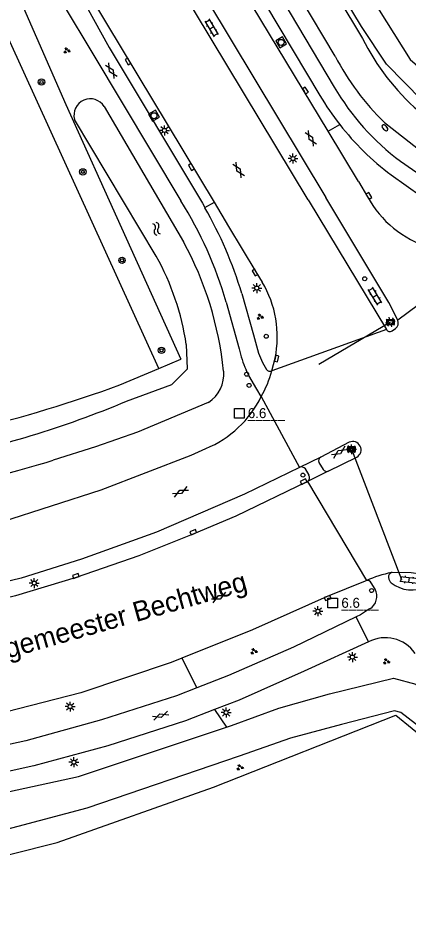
# Model space of a CAD drawing. Extents: x 133000 to 136000, y 400500 to 403500.
# Drawn here: x 133531.3 to 133580.3, y 400943.8 to 401055.6 of the extents above; entities that cross this region are included whole.
import ezdxf

# ---------------------------------------------------------------- set-up
doc = ezdxf.new("R2010")
doc.units = 0
for name, color, linetype in [('gg-afsc-draadraster', 7, 'Continuous'), ('gg-afsc-erfafscheiding', 7, 'Continuous'), ('gg-afsc-hekwerk', 7, 'Continuous'), ('gg-anno-openbare ruimte label', 7, 'Continuous'), ('gg-knt-verharding', 7, 'Continuous'), ('gg-knt-verharding nz', 7, 'Continuous'), ('gg-kntw-bovenkant insteek waterloop', 7, 'Continuous'), ('gt-anno-nummer hm paal', 7, 'Continuous'), ('gt-grn-groengrens', 7, 'Continuous'), ('gt-grn-weggrens', 7, 'Continuous'), ('gt-knt-lijn portaal', 7, 'Continuous'), ('gt-symb-boom', 7, 'Continuous'), ('gt-symb-brandkraan', 7, 'Continuous'), ('gt-symb-drukknoppaal', 7, 'Continuous'), ('gt-symb-gesloten verharding', 7, 'Continuous'), ('gt-symb-groenvak', 7, 'Continuous'), ('gt-symb-hm paal', 7, 'Continuous'), ('gt-symb-klinker verharding', 7, 'Continuous'), ('gt-symb-kolk', 7, 'Continuous'), ('gt-symb-lichtmast', 7, 'Continuous'), ('gt-symb-portaalmast', 7, 'Continuous'), ('gt-symb-rioolschacht', 7, 'Continuous'), ('gt-symb-verkeersregelinstallatiepaal', 7, 'Continuous'), ('gt-symb-watersymbool', 7, 'Continuous'), ('gt-symb-wegwijzer', 7, 'Continuous')]:
    doc.layers.add(name, color=color, linetype=linetype)

# ---------------------------------------------------------------- blocks, each defined once
blk = doc.blocks.new('gt0-RS')
at = {"layer": 'gt-symb-rioolschacht'}
blk.add_lwpolyline([(-0.5, -0.5), (0.5, -0.5), (0.5, 0.5), (-0.5, 0.5)], close=True, dxfattribs=at)
blk.add_circle((0, 0), 0.375, dxfattribs=at)
blk = doc.blocks.new('gt0-LMAST')
at = {"layer": 'gt-symb-lichtmast'}
for p, q in [((-0.18, 0.17), (-0.45, 0.44)), ((-0.01, 0.25), (-0.01, 0.62)), ((0.17, 0.17), (0.44, 0.44)), ((-0.26, 0), (-0.63, 0)), ((-0.18, -0.18), (-0.45, -0.45)), ((-0.01, -0.25), (-0.01, -0.63)), ((0.44, -0.45), (0.17, -0.18)), ((0.24, 0), (0.62, 0))]:
    blk.add_line(p, q, dxfattribs=at)
blk.add_circle((-0.01, 0), 0.25, dxfattribs=at)
blk = doc.blocks.new('gt0-KOLK')
at = {"layer": 'gt-symb-kolk'}
blk.add_lwpolyline([(0, 0), (0.38, 0), (0.38, 0.4), (-0.37, 0.4), (-0.37, 0), (0, 0)], dxfattribs=at)
blk = doc.blocks.new('gt0-GESVH1')
at = {"layer": 'gt-symb-gesloten verharding'}
for p, q in [((-0.99, -0.26), (0.01, 0.24)), ((0.01, -0.26), (-0.99, 0.24)), ((0.01, 0.24), (1.01, -0.26)), ((1.01, 0.24), (0.01, -0.26))]:
    blk.add_line(p, q, dxfattribs=at)
blk = doc.blocks.new('gt0-BR')
at = {"layer": 'gt-symb-brandkraan'}
for centre, radius, start, end in [((-0.24, 0), 0.206, 107.5669, 252.4331), ((0.6, -2.66), 3, 106.892, 107.5669), ((0, -0.69), 0.938, 73.108, 106.892), ((-0.6, -2.66), 3, 72.4331, 73.108), ((0.24, 0), 0.206, 287.567, 72.4331), ((0.6, 2.66), 3, 252.4331, 253.108), ((0, 0.69), 0.938, 253.108, 286.8921), ((-0.6, 2.66), 3, 286.8921, 287.567)]:
    blk.add_arc(centre, radius, start, end, dxfattribs=at)
blk = doc.blocks.new('gt0-WA')
at = {"layer": 'gt-symb-watersymbool'}
for centre, start, end in [((-0.32, 0.02), 28.0725, 151.9275), ((0.43, 0.42), 208.0725, 331.9275), ((-0.32, -0.43), 28.0725, 151.9275), ((0.43, -0.03), 208.0725, 331.9275)]:
    blk.add_arc(centre, 0.425, start, end, dxfattribs=at)
blk = doc.blocks.new('gt0-BOOM')
at = {"layer": 'gt-symb-boom'}
for radius in [0.4, 0.2]:
    blk.add_circle((0, 0), radius, dxfattribs=at)
blk = doc.blocks.new('gt0-GRVAK')
at = {"layer": 'gt-symb-groenvak'}
for p, q in [((-0.11, 0.19), (-0.23, 0.24)), ((-0.18, 0.15), (0.09, 0.15)), ((-0.09, 0.21), (-0.16, 0.32)), ((-0.05, 0.21), (-0.05, 0.39)), ((0, 0.21), (0.06, 0.32)), ((0.01, 0.19), (0.13, 0.24)), ((0.26, -0.05), (0.2, 0.06)), ((0.3, -0.05), (0.3, 0.13)), ((0.35, -0.05), (0.41, 0.06)), ((-0.25, -0.23), (-0.36, -0.18)), ((-0.32, -0.26), (-0.05, -0.26)), ((-0.23, -0.21), (-0.29, -0.1)), ((-0.18, -0.2), (-0.18, -0.02)), ((-0.14, -0.21), (-0.07, -0.1)), ((-0.12, -0.23), (0, -0.18)), ((0.24, -0.07), (0.12, -0.02)), ((0.17, -0.11), (0.44, -0.11)), ((0.37, -0.07), (0.49, -0.02))]:
    blk.add_line(p, q, dxfattribs=at)
blk = doc.blocks.new('gt0-KL1')
at = {"layer": 'gt-symb-klinker verharding'}
for p, q in [((-1.15, 0.3), (1.15, 0.3)), ((-1, -0.3), (-1, 0.3)), ((-0.5, 0.3), (-0.5, 0.45)), ((0, -0.3), (0, 0.3)), ((0.5, 0.3), (0.5, 0.45)), ((1, -0.3), (1, 0.3)), ((-1.15, -0.3), (1.15, -0.3)), ((-0.5, -0.45), (-0.5, -0.3)), ((0.5, -0.45), (0.5, -0.3))]:
    blk.add_line(p, q, dxfattribs=at)
blk = doc.blocks.new('gt0-WW')
at = {"layer": 'gt-symb-wegwijzer'}
blk.add_lwpolyline([(-0.5, 0.3), (-0.5, -0.29), (0.5, -0.29), (0.5, 0.3), (-0.5, 0.3)], dxfattribs=at)
blk.add_lwpolyline([(-0.42, -0.21), (0.42, -0.21), (0.42, 0.21), (-0.42, 0.21)], close=True, dxfattribs=at)
blk = doc.blocks.new('gt0-PORTM')
at = {"layer": 'gt-symb-portaalmast'}
for radius in [0.4, 0.33, 0.27, 0.21, 0.15]:
    blk.add_circle((0, 0), radius, dxfattribs=at)
blk = doc.blocks.new('gt0-VIPAAL')
at = {"layer": 'gt-symb-verkeersregelinstallatiepaal'}
blk.add_circle((0, 0), 0.25, dxfattribs=at)
blk = doc.blocks.new('gt0-HMpaal')
at = {"layer": 'gt-symb-hm paal'}
blk.add_lwpolyline([(-0.6, 0.6), (0.6, 0.6), (0.6, -0.6), (-0.6, -0.6)], close=True, dxfattribs=at)
blk = doc.blocks.new('gt0-DPAAL')
at = {"layer": 'gt-symb-drukknoppaal'}
blk.add_circle((0, 0), 0.25, dxfattribs=at)

msp = doc.modelspace()

# ---------------------------------------------------------------- linework, layer by layer
at = {"layer": 'gg-afsc-draadraster'}
for p, q in [((133548.98, 401011.54), (133551.74, 401012.71)), ((133544.11, 401009.48), (133548.98, 401011.54))]:
    msp.add_line(p, q, dxfattribs=at)
for points in [[(133548.98, 401011.54), (133526.85, 401060.17), (133529.97, 401061.6)], [(133529.97, 401061.6), (133537.32, 401044.74), (133544.3, 401029.21), (133551.74, 401012.71)]]:
    msp.add_lwpolyline(points, dxfattribs=at)
msp.add_arc((133486.69, 401165.26), 166.02, 276.8914, 290.2328, dxfattribs=at)
at = {"layer": 'gg-afsc-erfafscheiding'}
msp.add_lwpolyline([(133429.63, 400949.86), (133442.72, 400946.87), (133458.33, 400944.55), (133473.77, 400943.81), (133489.11, 400944.33), (133504.61, 400946.17), (133524.57, 400949.02), (133536.24, 400951.94), (133555.85, 400958.89), (133578.74, 400967.97), (133582.86, 400964.61), (133584.25, 400963.67), (133588.3, 400961.36)], dxfattribs=at)
at = {"layer": 'gg-afsc-hekwerk'}
msp.add_lwpolyline([(133654.12, 401074.5), (133649.97, 401072.09), (133618.45, 401053.28), (133591.98, 401037.34), (133586.65, 401040.93), (133582.05, 401045.23), (133577.57, 401049.8), (133574.45, 401054.54), (133571.28, 401059.77), (133563.26, 401072.86), (133558.49, 401080.51), (133555.19, 401085.65), (133544.2, 401100.25), (133542.35, 401102.86)], dxfattribs=at)
at = {"layer": 'gg-knt-verharding'}
for p, q in [((133555.97, 401032.46), (133539.51, 401059.87)), ((133574.07, 401035.04), (133570.25, 401041.38)), ((133579.32, 401037.61), (133583.23, 401034.9)), ((133574.07, 401035.04), (133575.19, 401033.13)), ((133578.14, 401035.89), (133581.94, 401033.2)), ((133567.74, 401032.74), (133577.57, 401016.44)), ((133554.46, 401032.33), (133554.79, 401031.76)), ((133557.8, 401029.4), (133555.97, 401032.46)), ((133559.41, 401020.95), (133560.88, 401015.76)), ((133557.46, 401019.89), (133559.07, 401014.02)), ((133578.28, 401016.28), (133578.71, 401016.58)), ((133563.19, 401011.24), (133563.6, 401012.84)), ((133572.9, 401002.27), (133569.32, 401000.4)), ((133569.32, 401000.4), (133566.64, 400999.11)), ((133570.26, 400998.64), (133573.84, 401000.41)), ((133569.09, 400999.73), (133569.61, 400998.84)), ((133567.38, 400998.92), (133567.83, 400998.11)), ((133570.26, 400998.64), (133567.66, 400997.33)), ((133576.14, 400983.79), (133575.65, 400984.57))]:
    msp.add_line(p, q, dxfattribs=at)
for points in [[(133511.05, 401131.47), (133517.82, 401121.34), (133525.52, 401111.31), (133540.84, 401093.84), (133547.12, 401085.68), (133552.59, 401077.56), (133559.03, 401067.09), (133571.02, 401046.91)], [(133532.39, 401100.25), (133539.33, 401092.38), (133545.48, 401084.43), (133550.79, 401076.49), (133557.25, 401065.96), (133569.21, 401045.87)], [(133570.25, 401041.38), (133552.27, 401071.2), (133549.82, 401075.17), (133546.79, 401079.84), (133543.81, 401084.1), (133539.85, 401089.26), (133531.44, 401099.47)], [(133528.3, 401096.2), (133534.98, 401088.2), (133540.26, 401081.34), (133544.79, 401074.72), (133549.02, 401067.9), (133569.97, 401033.05)], [(133567.74, 401032.74), (133547.46, 401066.52), (133546.83, 401067.47), (133546.09, 401068.39), (133538.43, 401076.32), (133537.32, 401077.61), (133536.35, 401079.01), (133526.68, 401095.05)], [(133538.14, 401060.27), (133542.77, 401051.88), (133554.46, 401032.33)], [(133536.32, 401058.59), (133536.99, 401057.3), (133540.72, 401051.12), (133551.77, 401032.6)], [(133578.98, 401017.6), (133577.87, 401019.82), (133569.97, 401033.05)], [(133561.99, 401022.41), (133561.23, 401023.69), (133557.8, 401029.4)], [(133560.88, 401015.76), (133561.51, 401013.45), (133562, 401012.3), (133562.51, 401011.43)], [(133561.85, 401008.02), (133561.28, 401008.94), (133560.3, 401010.66), (133559.94, 401011.38)], [(133491.05, 400986.34), (133504.02, 400987.36), (133516.73, 400989.32), (133529.29, 400992.26), (133541.74, 400996.27), (133553.07, 401000.64), (133554.89, 401001.47)], [(133566.64, 400999.11), (133559.73, 400995.72), (133548.7, 400990.94), (133539.29, 400987.58), (133531.7, 400985.17), (133521.97, 400982.82), (133497.29, 400979.24), (133488.29, 400978.81)], [(133553.76, 400971.39), (133551.21, 400970.39), (133541.82, 400967.37), (133532.32, 400964.74), (133522.45, 400962.6), (133512.34, 400960.97), (133502.83, 400959.79), (133492.83, 400959.05), (133482.34, 400958.86), (133472.72, 400959.38), (133462.97, 400960.8), (133450.31, 400963.54), (133438.45, 400966.57), (133427.13, 400970.26), (133413.3, 400975.7), (133361.85, 400997.16)], [(133567.66, 400997.33), (133558.65, 400992.98), (133553.39, 400990.76), (133546.47, 400987.99), (133538.63, 400985.26), (133531.01, 400982.95), (133522.97, 400981.01), (133514.62, 400979.4), (133508.32, 400978.46), (133500.37, 400977.5), (133493.2, 400977.05), (133486.8, 400976.9)], [(133582.82, 400985.41), (133581.82, 400985.68), (133580.66, 400985.86), (133578.28, 400985.89), (133578.2, 400985.87)], [(133575.07, 400984.87), (133574.91, 400984.8), (133570.12, 400982.87), (133560.74, 400978.69), (133551.9, 400975.12)], [(133575.46, 400981.32), (133574.3, 400980.57), (133573.77, 400980.31)], [(133573.77, 400980.31), (133565.89, 400976.49), (133557.74, 400972.96), (133553.76, 400971.39)], [(133575.3, 400977.16), (133567.24, 400973.47), (133559.06, 400969.84), (133555.98, 400968.66)], [(133551.9, 400975.12), (133550.55, 400974.58), (133539.21, 400970.78), (133526.62, 400967.55), (133511.93, 400964.85), (133497.02, 400963.29), (133484.02, 400962.79), (133470.14, 400963.92), (133455.87, 400967.26)], [(133555.98, 400968.66), (133552.35, 400967.26), (133542.58, 400964.11), (133533.31, 400961.57), (133522.88, 400959.29), (133512.79, 400957.65), (133502.87, 400956.47), (133493.05, 400955.74), (133481.99, 400955.49), (133472.41, 400955.95), (133462.34, 400957.3), (133449.49, 400960.09), (133437.46, 400963.16), (133425.93, 400966.91), (133412, 400972.4)]]:
    msp.add_lwpolyline(points, dxfattribs=at)
for centre, radius, start, end in [((133598.45, 401063.03), 31.82, 210.4464, 233.0352), ((133598.76, 401063.31), 34.31, 210.5629, 217.9652), ((133598.72, 401063.3), 34.27, 217.9817, 233.0969), ((133587, 401039.61), 13.48, 208.7612, 252.5975), ((133508, 401005.39), 51.54, 16.3434, 31.8674), ((133509.26, 401005.89), 52.36, 16.722, 29.6034), ((133550.22, 401015.51), 13.64, 348.703, 30.3924), ((133578.26, 401017.24), 0.801, 304.2152, 26.3919), ((133577.99, 401016.69), 0.499, 211.0486, 304.2877), ((133572.41, 401016.97), 13.66, 192.4537, 204.1293), ((133550.04, 401014.83), 13.63, 330.0299, 344.7253), ((133562.95, 401011.71), 0.526, 212.4575, 296.5901), ((133549.76, 401013.89), 13.44, 292.4477, 334.1194), ((133573.34, 401001.32), 1.04, 298.5485, 114.8766), ((133569.59, 400999.93), 0.54, 119.5814, 202.2783), ((133566.89, 400998.54), 0.626, 37.613, 113.7385), ((133567.35, 400997.81), 0.569, 302.5405, 32.6336), ((133570.04, 400999.09), 0.5, 210.1484, 296.3729), ((133578.34, 400985.37), 0.524, 105.7974, 192.0557), ((133575.19, 400984.39), 0.494, 21.5496, 104.2993), ((133578.77, 400985.31), 0.94, 183.3636, 229.9045), ((133574.49, 400982.91), 1.87, 301.3162, 28.2518), ((133580.73, 400987.8), 4.11, 231.2837, 298.0314), ((133577.43, 400973.17), 4.52, 34.4385, 118.1165)]:
    msp.add_arc(centre, radius, start, end, dxfattribs=at)
at = {"layer": 'gg-knt-verharding nz'}
msp.add_arc((133581, 400971.71), 14.44, 101.2117, 114.255, dxfattribs=at)
at = {"layer": 'gg-kntw-bovenkant insteek waterloop'}
for p, q in [((133560.2, 401076.98), (133574.57, 401053.03)), ((133571.13, 401050.8), (133556.75, 401075.06)), ((133542.14, 401044.47), (133552.11, 401027.46)), ((133548.67, 401025.65), (133538.41, 401042.86))]:
    msp.add_line(p, q, dxfattribs=at)
for points in [[(133577.31, 401042.47), (133589.11, 401033.21), (133591.21, 401032.71), (133598.69, 401035.82), (133600.28, 401037.01), (133616.34, 401046.89), (133621.18, 401049.95), (133630.16, 401055.49), (133640.45, 401061.77), (133653.64, 401069.43), (133666.65, 401076.64), (133672.96, 401079.92), (133673.67, 401080.26), (133673.34, 401080.87)], [(133544.95, 401007.43), (133550.61, 401009.54), (133552.59, 401011.5), (133552.45, 401014.55)], [(133555.21, 401007.28), (133546.3, 401003.54), (133541.04, 401001.69), (133535.72, 401000)], [(133588.3, 400961.36), (133588.19, 400961.45), (133579.36, 400968.3), (133578.58, 400968.5), (133571.94, 400966.8), (133565.51, 400965.05), (133559.08, 400962.78), (133539.96, 400956.26), (133519.92, 400950.94), (133499.85, 400947.79), (133478.53, 400946.66), (133457.67, 400947.65), (133436.61, 400950.84), (133415.79, 400956.04), (133374.48, 400971.81), (133356.68, 400978.5), (133345.41, 400982.38), (133332.88, 400986.15), (133319.75, 400989.75), (133303.12, 400993.15), (133285.23, 400995.89), (133269.89, 400998.39), (133256.47, 400999.27)], [(133557.49, 400966.44), (133558.12, 400966.65), (133564.04, 400968.84), (133570.43, 400970.62), (133578.45, 400972.61), (133581.25, 400971.86), (133587.31, 400967.21)], [(133499.15, 400952.85), (133519.05, 400955.94), (133538.92, 400960.25), (133557.49, 400966.44)]]:
    msp.add_lwpolyline(points, dxfattribs=at)
for centre, radius, start, end in [((133601.65, 401066.65), 30.32, 206.6933, 228.5478), ((133600.33, 401066), 32.92, 207.4991, 225.6264), ((133540.4, 401043.38), 2.06, 31.8252, 194.9124), ((133514.19, 401006.83), 43.16, 5.8268, 28.5427), ((133519.87, 401009.67), 32.94, 8.5165, 29.03), ((133552.99, 401010.81), 4.17, 302.2099, 5.5613), ((133495.85, 401124.66), 127.1, 281.2461, 292.7258), ((133482.56, 401176.31), 184.15, 277.5891, 286.7789)]:
    msp.add_arc(centre, radius, start, end, dxfattribs=at)
at = {"layer": 'gt-grn-groengrens'}
for p, q in [((133570.25, 401041.38), (133571.71, 401042.21)), ((133554.79, 401031.76), (133555.97, 401032.46)), ((133551.9, 400975.12), (133553.76, 400971.39)), ((133555.98, 400968.66), (133557.49, 400966.44))]:
    msp.add_line(p, q, dxfattribs=at)
msp.add_lwpolyline([(133547.02, 401103.88), (133580.55, 401050.39), (133587.72, 401044.13), (133591.74, 401041.32), (133652.29, 401077.19)], dxfattribs=at)
at = {"layer": 'gt-grn-weggrens'}
for p, q in [((133591.25, 401026.76), (133578.98, 401017.6)), ((133577.57, 401016.44), (133563.19, 401011.24)), ((133561.85, 401008.02), (133566.64, 400999.11)), ((133567.66, 400997.33), (133575.07, 400984.87)), ((133575.3, 400977.16), (133573.77, 400980.31))]:
    msp.add_line(p, q, dxfattribs=at)
at = {"layer": 'gt-knt-lijn portaal'}
for p, q in [((133578.06, 401017.37), (133569.1, 401012.05)), ((133573.19, 401001.38), (133579.44, 400985.02))]:
    msp.add_line(p, q, dxfattribs=at)

# ---------------------------------------------------------------- block references
at = {"layer": 'gt-symb-boom'}
for p in [(133534.27, 401047.55), (133539.46, 401036.26), (133544.38, 401025.13), (133549.33, 401013.83)]:
    msp.add_blockref('gt0-BOOM', p, dxfattribs=at)
at = {"layer": 'gt-symb-brandkraan', "rotation": -44.43273359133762}
msp.add_blockref('gt0-BR', (133577.37, 401041.81), dxfattribs=at)
at = {"layer": 'gt-symb-drukknoppaal'}
msp.add_blockref('gt0-DPAAL', (133560.02, 401010.82), dxfattribs=at)
at = {"layer": 'gt-symb-gesloten verharding'}
for p, rotation in [((133543.04, 401048.98), -58.996932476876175), ((133568.08, 401040.49), -58.99693247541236), ((133559.01, 401036.51), -58.99693247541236), ((133571.64, 401001.02), 33.244937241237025), ((133551.72, 400996.03), 26.66750217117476), ((133556.58, 400982.76), 26.66750217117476), ((133549.21, 400967.9), 20.35496118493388)]:
    msp.add_blockref('gt0-GESVH1', p, dxfattribs=dict(at, rotation=rotation))
at = {"layer": 'gt-symb-groenvak'}
for p in [(133537.43, 401051.51), (133561.68, 401018.03), (133560.92, 400975.98), (133577.54, 400974.7), (133559.16, 400961.38)]:
    msp.add_blockref('gt0-GRVAK', p, dxfattribs=at)
at = {"layer": 'gt-symb-hm paal'}
for p in [(133559.09, 401005.9), (133570.83, 400982.05)]:
    msp.add_blockref('gt0-HMpaal', p, dxfattribs=at)
at = {"layer": 'gt-symb-klinker verharding'}
for p, rotation in [((133555.61, 401054.37), -58.996932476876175), ((133576.14, 401020.64), 121.00306752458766), ((133580.41, 400984.96), -6.143995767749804)]:
    msp.add_blockref('gt0-KL1', p, dxfattribs=dict(at, rotation=rotation))
at = {"layer": 'gt-symb-kolk'}
for p, rotation in [((133545.29, 401050.25), 121.00306752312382), ((133567.23, 401046.39), -58.918270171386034), ((133553.26, 401036.97), 121.00306752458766), ((133575.19, 401033.13), -58.279939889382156), ((133561.23, 401023.69), 120.4626400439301), ((133563.6, 401012.84), -104.30027744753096), ((133567.26, 400997.13), 26.36005821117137), ((133553.39, 400990.76), 22.89759102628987), ((133538.63, 400985.26), 19.141373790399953), ((133570.12, 400982.87), -158.04971540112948)]:
    msp.add_blockref('gt0-KOLK', p, dxfattribs=dict(at, rotation=rotation))
at = {"layer": 'gt-symb-lichtmast'}
for p in [(133549.71, 401041.48), (133565.84, 401037.93), (133561.3, 401021.65), (133573.19, 401001.38), (133533.36, 400984.56), (133568.97, 400981.02), (133573.3, 400975.26), (133537.87, 400969.03), (133557.45, 400968.28), (133538.34, 400962.04)]:
    msp.add_blockref('gt0-LMAST', p, dxfattribs=at)
at = {"layer": 'gt-symb-lichtmast', "rotation": 102.70273191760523}
msp.add_blockref('gt0-LMAST', (133578.05, 401017.38), dxfattribs=at)
at = {"layer": 'gt-symb-portaalmast'}
msp.add_blockref('gt0-PORTM', (133573.19, 401001.38), dxfattribs=at)
at = {"layer": 'gt-symb-rioolschacht'}
for p, rotation in [((133564.35, 401052.54), 120.05032329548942), ((133548.39, 401043.32), -150.25511869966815)]:
    msp.add_blockref('gt0-RS', p, dxfattribs=dict(at, rotation=rotation))
at = {"layer": 'gt-symb-verkeersregelinstallatiepaal'}
for p in [(133574.84, 401022.82), (133562.47, 401015.59), (133560.33, 401009.42), (133567.08, 400998.13), (133575.7, 400983.62)]:
    msp.add_blockref('gt0-VIPAAL', p, dxfattribs=at)
at = {"layer": 'gt-symb-watersymbool', "rotation": -69.02828944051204}
msp.add_blockref('gt0-WA', (133548.69, 401029.15), dxfattribs=at)
at = {"layer": 'gt-symb-wegwijzer'}
for p in [(133578.06, 401017.37), (133573.19, 401001.38)]:
    msp.add_blockref('gt0-WW', p, dxfattribs=at)

# ---------------------------------------------------------------- texts
at = {"layer": 'gg-anno-openbare ruimte label'}
msp.add_text('Burgemeester Bechtweg', height=2.5, rotation=15.9, dxfattribs=at).set_placement((133525.06, 400973.64))
at = {"layer": 'gt-anno-nummer hm paal'}
for p in [(133560.17, 401005.3), (133571.91, 400981.45)]:
    msp.add_text('6.6', height=1.25, dxfattribs=at).set_placement(p)
at = {"layer": 'gt-symb-hm paal'}
for p in [(133560.17, 401005.3), (133571.91, 400981.45)]:
    msp.add_text('_____', height=1.25, dxfattribs=at).set_placement(p)

doc.saveas('drawing.dxf')
